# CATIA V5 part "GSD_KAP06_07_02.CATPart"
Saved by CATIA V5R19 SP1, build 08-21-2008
Part number: GSD_SWEEP_LINE_01
Definition: Beispielmodell für die Funktion Translation - Linie / Sweep - Line.
Description: CATIA V5 Flächenmodellierung  Copyright (c) 2009 Maik Hertha IT Consultants
Bounding box of the stored display mesh (mm): x -120.363 to 112.322, y -60 to -3.164, z 0 to 0
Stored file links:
  \GSD_BUCH_UEBUNG\GSD_KAP06_07_02.CATPart
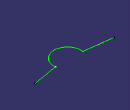
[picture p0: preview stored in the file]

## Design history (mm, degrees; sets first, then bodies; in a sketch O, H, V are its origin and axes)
AxisSystem1: origin (0, 0, 0), X (1, 0, 0), Y (0, 1, 0), Z (0, 0, 1)
Set1
  Sketch1 on xy-plane, origin (0, 0, 0), H (1, 0, 0), V (0, 1, 0)
    line L1 (112.3223, -3.1639) -> (39.7788, -15.7993)
    arc A1 centre (0, -20) radius 40 from (39.7788, -15.7993) to (-39.6088, -14.4195) cw
    point P3 (0, -20)
    line L2 (-39.6088, -14.4195) -> (-120.363, -4.0213)
    construction line L3 (13.9125, -20) -> (-11.1781, -20)
    construction line L4 (39.2477, 0) -> (-28.2488, 0)
    point P8 (39.2477, 0)
    construction line L5 (0, 7.9755) -> (0, -63.4676)
    point P10 (0, 7.9755)
    curve C1
    spline S1 through (-120.9377, -13.3542) (-46.9511, -26.3635) (48.4251, -27.4184) (115.1771, -16.8703)
    curve C2
    distance L3 L4 = 20
    radius A1 = 40
    horizontal: L3 H, L4 H
    coincidence: P8 H, P10 V, P3 L5, P3 L3
    vertical: L5 V
Set2
  DatumCurve1: linked copy from another document
Set3
  DatumCurve2: linked copy from another document
Body1 (main body)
